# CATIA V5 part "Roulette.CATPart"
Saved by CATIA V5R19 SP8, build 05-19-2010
Part number: Galet de roulement
Bounding box of the stored display mesh (mm): x -7.293 to 7.293, y -7.3 to 7.3, z -2.5 to 2.5
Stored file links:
  D:\Documents\1_Travail\1 - ac-limoges.fr\ac-limoges.fr\Emmanuel Maynard - STI2D_Turgot\1 - IT-I2D\Activités_IT_Première\IT_3_Abris_bus\Maquettes numériques\Abribus_eleve\Roulette.CATPart
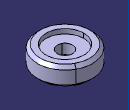
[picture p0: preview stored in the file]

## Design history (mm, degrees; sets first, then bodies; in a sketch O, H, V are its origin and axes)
AxisSystem1: origin (0, 0, 0), X (1, 0, 0), Y (0, 1, 0), Z (0, 0, 1)
Body1 (main body)
  Sketch1 on YZ plane of AxisSystem1, origin (0, 0, 0), H (0, 1, 0), V (0, 0, 1)
    axis line L1 (0, 17.0746) -> (0, -25.0944)
    point P1 (0, 17.0746)
    line L2 (2, 2.5) -> (6.5, 2.5)
    line L3 (7.3, 1.7) -> (7.3, -1.7)
    point P3 (7.3, -2.5)
    line L4 (6.5, -2.5) -> (2, -2.5)
    line L5 (2, 2.5) -> (2, -2.5)
    line L6 (6.5, 2.5) -> (7.3, 1.7)
    point P7 (7.3, 1.7)
    line L7 (7.3, -1.7) -> (6.5, -2.5)
    point P8 (7.3, -1.7)
    distance V L3 = 7.3
    distance L2 H = 2.5
    distance L5 L1 = 2
    angle L2 L6 = 45
    angle L3 L7 = 45
    distance P7 L2 = 0.8
    distance P8 L4 = 0.8
    distance L4 L2 = 5
    coincidence: P1 V, L3 P3, L4 P3
    vertical: L1 V, L3 V, L5 V
    horizontal: L2 H
  Shaft1: profile Sketch1, axis Sketch1.L1, angle 360
  Sketch2 on face of Shaft1 from Sketch1.L2, origin (0, 0, 2.5), H (1, 0, 0), V (0, 1, 0)
    circle A1 centre (0, 0) radius 5
    radius A1 = 5
  Pocket1: profile Sketch2, direction (0, 0, -1), length 1.2
  Sketch3 on face of Shaft1 from Sketch1.L4, origin (0, 0, -2.5), H (1, 0, 0), V (0, -1, 0)
    circle A1 centre (0, 0) radius 5
    radius A1 = 5
  Pocket2: profile Sketch3, direction (0, 0, 1), length 1.2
